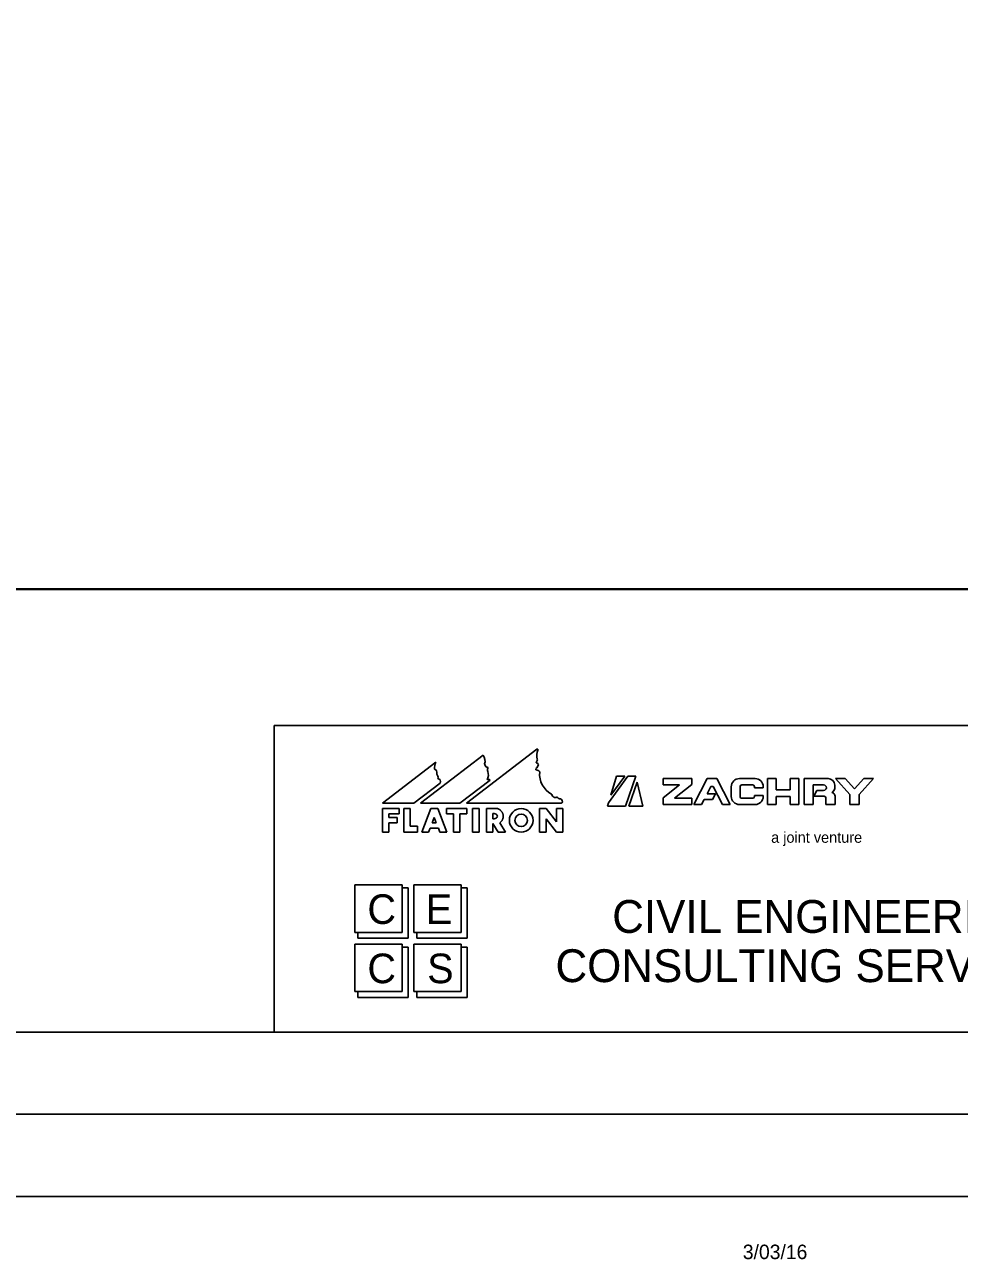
# Model space of a CAD drawing. Extents: x -2251 to 10196, y -13470 to 1199.
# Drawn here: x 6237.7 to 6522.4, y -13469.8 to -13093.7 of the extents above; entities that cross this region are included whole.
import ezdxf

# ---------------------------------------------------------------- set-up
doc = ezdxf.new("R2010")
doc.units = 0
for name, color, linetype in [('Level 3', 7, 'Continuous'), ('RD_SHT_Bndy', 7, 'Continuous'), ('RD_SHT_Iplotshp', 7, 'Continuous'), ('RD_SHT_Logo', 7, 'Continuous'), ('RD_SHT_Misc1', 7, 'Continuous'), ('RD_SHT_Snap', 7, 'Continuous'), ('RD_SHT_TX', 7, 'Continuous'), ('RD_TX_RoadID', 7, 'Continuous')]:
    doc.layers.add(name, color=color, linetype=linetype)

msp = doc.modelspace()

# ---------------------------------------------------------------- linework, layer by layer
at = {"layer": 'Level 3'}
msp.add_line((6465.07, -13363.99), (6465.07, -13363.99), dxfattribs=at)
msp.add_line((6465.07, -13363.99), (6465.07, -13363.99), dxfattribs=at)
msp.add_line((6465.07, -13363.99), (6465.07, -13363.99), dxfattribs=at)
msp.add_line((6465.07, -13363.99), (6465.07, -13363.99), dxfattribs=at)
at = {"layer": 'RD_SHT_Bndy'}
for p, q in [((5103.1, -13400.65), (6778.1, -13400.65)), ((6791.65, -13425.65), (5031.65, -13425.65)), ((6791.6, -13450.7), (5031.6, -13450.65))]:
    msp.add_line(p, q, dxfattribs=at)
msp.add_lwpolyline([(5153.4, -12401.26), (6731.08, -12401.26), (6731.08, -13265.57), (5153.4, -13265.57)], close=True, dxfattribs=at)
at = {"layer": 'RD_SHT_Iplotshp'}
msp.add_lwpolyline([(4996.65, -12325.65), (6796.65, -12325.65), (6796.65, -13425.65), (4996.65, -13425.65)], close=True, dxfattribs=at)
at = {"layer": 'RD_SHT_Logo'}
for p, q in [((6377.35, -13316.27), (6358.31, -13330.86)), ((6372.32, -13330.86), (6393.74, -13314.44)), ((6346.7, -13330.86), (6362.98, -13318.38)), ((6370.3, -13330.86), (6379.48, -13323.82)), ((6415.56, -13330.77), (6421.47, -13322.59)), ((6420.48, -13322.59), (6416.24, -13328.47)), ((6416.24, -13328.47), (6417.96, -13322.59)), ((6417.96, -13322.59), (6420.48, -13322.59)), ((6423.82, -13322.59), (6420.68, -13331.76)), ((6421.47, -13322.59), (6423.82, -13322.59)), ((6440.93, -13323.35), (6432.22, -13323.35)), ((6432.22, -13323.35), (6432.22, -13325.3)), ((6440.93, -13325.16), (6440.93, -13323.35)), ((6445.58, -13323.35), (6441.53, -13331.3)), ((6448.58, -13323.35), (6445.58, -13323.35)), ((6452.63, -13331.3), (6448.58, -13323.35)), ((6455.44, -13323.35), (6460.18, -13323.35)), ((6466.62, -13323.35), (6464.02, -13323.35)), ((6464.02, -13323.35), (6464.02, -13331.3)), ((6466.62, -13326.8), (6466.62, -13323.35)), ((6470.9, -13323.35), (6470.9, -13326.8)), ((6473.51, -13323.35), (6470.9, -13323.35)), ((6473.5, -13331.3), (6473.51, -13323.35)), ((6482.43, -13323.35), (6475.13, -13323.35)), ((6475.13, -13323.35), (6475.13, -13331.3)), ((6484.68, -13323.35), (6487.64, -13323.35)), ((6489.08, -13328.24), (6484.68, -13323.35)), ((6487.64, -13323.35), (6490.48, -13326.51)), ((6490.48, -13326.51), (6493.32, -13323.35)), ((6496.28, -13323.35), (6491.88, -13328.24)), ((6493.32, -13323.35), (6496.28, -13323.35)), ((6364.27, -13324.74), (6356.29, -13330.86)), ((6424.24, -13324.44), (6421.74, -13331.76)), ((6425.99, -13331.76), (6424.24, -13324.44)), ((6437.2, -13325.3), (6432.22, -13329.24)), ((6432.22, -13325.3), (6437.2, -13325.3)), ((6435.63, -13329.35), (6440.93, -13325.16)), ((6445.57, -13327.99), (6446.71, -13325.75)), ((6446.71, -13325.75), (6447.44, -13325.75)), ((6447.44, -13325.75), (6450.27, -13331.3)), ((6452.94, -13328.8), (6452.94, -13325.85)), ((6455.64, -13325.8), (6455.64, -13328.85)), ((6459.48, -13325.3), (6456.14, -13325.3)), ((6459.98, -13326.15), (6459.98, -13325.8)), ((6462.68, -13326.15), (6459.98, -13326.15)), ((6462.68, -13325.85), (6462.68, -13326.15)), ((6470.9, -13326.8), (6466.62, -13326.8)), ((6477.83, -13331.3), (6477.83, -13325.31)), ((6477.83, -13325.31), (6481.07, -13325.31)), ((6479.03, -13326.97), (6478.11, -13328.77)), ((6481.07, -13326.97), (6479.03, -13326.97)), ((6483.68, -13327.6), (6483.68, -13327.47)), ((6484.43, -13326.36), (6484.43, -13325.35)), ((6356.29, -13330.86), (6346.7, -13330.86)), ((6358.31, -13330.86), (6370.3, -13330.86)), ((6401.19, -13330.86), (6372.32, -13330.86)), ((6415.27, -13331.76), (6415.56, -13330.77)), ((6432.22, -13329.24), (6432.22, -13331.3)), ((6432.22, -13331.3), (6440.93, -13331.3)), ((6440.93, -13329.35), (6435.63, -13329.35)), ((6440.93, -13331.3), (6440.93, -13329.35)), ((6441.53, -13331.3), (6443.88, -13331.3)), ((6443.88, -13331.3), (6444.65, -13329.79)), ((6444.65, -13329.79), (6447.23, -13329.79)), ((6448.15, -13327.99), (6445.57, -13327.99)), ((6447.23, -13329.79), (6448.15, -13327.99)), ((6450.27, -13331.3), (6452.63, -13331.3)), ((6460.18, -13331.3), (6455.44, -13331.3)), ((6456.14, -13329.35), (6459.48, -13329.35)), ((6459.98, -13328.5), (6462.68, -13328.5)), ((6459.98, -13328.85), (6459.98, -13328.5)), ((6462.68, -13328.5), (6462.68, -13328.8)), ((6464.02, -13331.3), (6466.62, -13331.3)), ((6466.62, -13331.3), (6466.62, -13328.8)), ((6466.62, -13328.8), (6470.9, -13328.8)), ((6470.9, -13328.8), (6470.9, -13331.3)), ((6470.9, -13331.3), (6473.5, -13331.3)), ((6475.13, -13331.3), (6477.83, -13331.3)), ((6478.11, -13328.77), (6481.24, -13328.77)), ((6481.74, -13329.27), (6481.74, -13331.3)), ((6481.74, -13331.3), (6484.54, -13331.3)), ((6484.54, -13331.3), (6484.54, -13328.76)), ((6489.08, -13331.3), (6489.08, -13328.24)), ((6491.88, -13331.3), (6489.08, -13331.3)), ((6491.88, -13328.24), (6491.88, -13331.3)), ((6346.72, -13339.7), (6346.72, -13332.5)), ((6346.72, -13332.5), (6351.82, -13332.5)), ((6351.82, -13334.15), (6348.67, -13334.15)), ((6348.67, -13334.15), (6348.67, -13335.21)), ((6348.67, -13335.21), (6351.22, -13335.21)), ((6351.22, -13335.21), (6351.22, -13336.86)), ((6351.82, -13332.5), (6351.82, -13334.15)), ((6355.12, -13332.5), (6353.17, -13332.5)), ((6353.17, -13332.5), (6353.17, -13339.7)), ((6355.12, -13337.9), (6355.12, -13332.5)), ((6361.42, -13332.5), (6358.65, -13339.71)), ((6363.52, -13332.5), (6361.42, -13332.5)), ((6361.83, -13336.86), (6362.47, -13335.2)), ((6362.47, -13335.2), (6363.1, -13336.86)), ((6366.28, -13339.71), (6363.52, -13332.5)), ((6366.22, -13334.15), (6366.22, -13332.5)), ((6366.22, -13332.5), (6372.37, -13332.5)), ((6368.32, -13334.15), (6366.22, -13334.15)), ((6368.32, -13339.71), (6368.32, -13334.15)), ((6372.37, -13334.15), (6370.27, -13334.15)), ((6370.27, -13334.15), (6370.27, -13339.71)), ((6372.37, -13332.5), (6372.37, -13334.15)), ((6374.17, -13339.71), (6374.17, -13332.5)), ((6374.17, -13332.5), (6376.12, -13332.5)), ((6376.12, -13332.5), (6376.12, -13339.71)), ((6381.8, -13332.5), (6378.38, -13332.5)), ((6378.38, -13332.5), (6378.38, -13339.71)), ((6380.33, -13335.66), (6380.33, -13334.01)), ((6396.52, -13332.5), (6394.57, -13332.5)), ((6394.57, -13332.5), (6394.57, -13339.71)), ((6399.67, -13336.53), (6396.52, -13332.5)), ((6401.62, -13332.5), (6399.67, -13332.5)), ((6399.67, -13332.5), (6399.67, -13336.53)), ((6401.62, -13339.71), (6401.62, -13332.5)), ((6420.68, -13331.76), (6415.27, -13331.76)), ((6421.74, -13331.76), (6425.99, -13331.76)), ((6351.22, -13336.86), (6348.67, -13336.86)), ((6348.67, -13336.86), (6348.67, -13339.7)), ((6357.37, -13337.9), (6355.12, -13337.9)), ((6357.37, -13339.71), (6357.37, -13337.9)), ((6360.74, -13339.71), (6361.2, -13338.51)), ((6361.2, -13338.51), (6363.74, -13338.51)), ((6363.1, -13336.86), (6361.83, -13336.86)), ((6363.74, -13338.51), (6364.2, -13339.71)), ((6380.33, -13339.71), (6380.33, -13337.02)), ((6380.33, -13337.02), (6381.94, -13339.71)), ((6384.16, -13339.71), (6382.43, -13336.82)), ((6396.52, -13339.71), (6396.52, -13335.67)), ((6396.52, -13335.67), (6399.67, -13339.71)), ((6348.67, -13339.7), (6346.72, -13339.7)), ((6353.17, -13339.7), (6357.37, -13339.71)), ((6358.65, -13339.71), (6360.74, -13339.71)), ((6364.2, -13339.71), (6366.28, -13339.71)), ((6370.27, -13339.71), (6368.32, -13339.71)), ((6376.12, -13339.71), (6374.17, -13339.71)), ((6378.38, -13339.71), (6380.33, -13339.71)), ((6381.94, -13339.71), (6384.16, -13339.71)), ((6394.57, -13339.71), (6396.52, -13339.71)), ((6399.67, -13339.71), (6401.62, -13339.71)), ((6352.67, -13355.79), (6338.28, -13355.79)), ((6338.28, -13355.79), (6338.28, -13370.23)), ((6352.67, -13370.23), (6352.67, -13355.79)), ((6352.67, -13355.79), (6352.67, -13370.23)), ((6354.48, -13356.7), (6352.67, -13356.7)), ((6354.48, -13372.03), (6354.48, -13356.7)), ((6370.67, -13355.79), (6356.27, -13355.79)), ((6356.27, -13355.79), (6356.27, -13370.23)), ((6370.67, -13370.23), (6370.67, -13355.79)), ((6370.67, -13355.79), (6370.67, -13370.23)), ((6372.48, -13356.7), (6370.67, -13356.7)), ((6372.48, -13372.03), (6372.48, -13356.7)), ((6338.28, -13370.23), (6352.67, -13370.23)), ((6352.67, -13370.23), (6339.17, -13370.23)), ((6339.17, -13370.23), (6339.17, -13372.03)), ((6339.17, -13372.03), (6354.48, -13372.03)), ((6356.27, -13370.23), (6370.67, -13370.23)), ((6370.67, -13370.23), (6357.18, -13370.23)), ((6357.18, -13370.23), (6357.18, -13372.03)), ((6357.18, -13372.03), (6372.48, -13372.03)), ((6352.67, -13373.84), (6338.28, -13373.84)), ((6338.28, -13373.84), (6338.28, -13388.27)), ((6352.67, -13388.27), (6352.67, -13373.84)), ((6352.67, -13373.84), (6352.67, -13388.27)), ((6354.48, -13374.74), (6352.67, -13374.74)), ((6354.48, -13390.07), (6354.48, -13374.74)), ((6370.67, -13373.84), (6356.27, -13373.84)), ((6356.27, -13373.84), (6356.27, -13388.27)), ((6370.67, -13388.27), (6370.67, -13373.84)), ((6370.67, -13373.84), (6370.67, -13388.27)), ((6372.48, -13374.74), (6370.67, -13374.74)), ((6372.48, -13390.07), (6372.48, -13374.74)), ((6338.28, -13388.27), (6352.67, -13388.27)), ((6352.67, -13388.27), (6339.17, -13388.27)), ((6339.17, -13388.27), (6339.17, -13390.07)), ((6339.17, -13390.07), (6354.48, -13390.07)), ((6356.27, -13388.27), (6370.67, -13388.27)), ((6370.67, -13388.27), (6357.18, -13388.27)), ((6357.18, -13388.27), (6357.18, -13390.07)), ((6357.18, -13390.07), (6372.48, -13390.07))]:
    msp.add_line(p, q, dxfattribs=at)
for radius in [3.6, 1.9]:
    msp.add_circle((6388.95, -13336.1), radius, dxfattribs=at)
for centre, radius, start, end in [((6375.05, -13318.02), 2.89, 342.0343, 37.2653), ((6397.87, -13316.34), 4.17, 156.4699, 195.3053), ((6393.86, -13314.6), 0.2, 336.4699, 127.4657), ((6366.29, -13320.12), 3.74, 152.2252, 185.8662), ((6377.99, -13318.97), 0.2, 162.0343, 220.8638), ((6376.86, -13319.95), 1.3, 11.8745, 40.8638), ((6378.32, -13319.64), 0.2, 191.8745, 279.8173), ((6378.44, -13320.33), 0.499, 44.4799, 99.8173), ((6379.5, -13320.72), 0.843, 144.641, 212.5499), ((6378.65, -13320.12), 0.2, 324.641, 44.4799), ((6393.57, -13320.5), 0.2, 133.0036, 262.3069), ((6391.59, -13318.37), 2.7, 313.0036, 343.6807), ((6393.73, -13318.39), 0.2, 129.4079, 246.863), ((6393.13, -13317.66), 0.749, 309.4079, 17.0499), ((6393.27, -13319.47), 0.973, 20.4113, 66.863), ((6362.1, -13321.62), 1.21, 351.6466, 67.1294), ((6364.29, -13321.94), 1, 171.6466, 221.9371), ((6363.11, -13323.01), 0.592, 327.6019, 41.9371), ((6363.3, -13324.33), 1.05, 337.4201, 73.1261), ((6375.8, -13322.18), 3.16, 331.2486, 18.4584), ((6378.92, -13324.44), 0.827, 48.0701, 115.7229), ((6393.31, -13322.44), 1.76, 45.283, 82.3069), ((6394.4, -13321.33), 0.2, 353.8329, 45.283), ((6401.36, -13322.08), 6.8, 173.8329, 242.3928), ((6455.44, -13325.85), 2.5, 89.9984, 179.9984), ((6460.18, -13325.85), 2.5, 359.9984, 89.9984), ((6482.43, -13325.35), 2, 359.9984, 89.9984), ((6456.14, -13325.8), 0.5, 89.9984, 179.9984), ((6459.48, -13325.8), 0.5, 359.9984, 89.9984), ((6481.07, -13326.14), 0.831, 269.9984, 89.9984), ((6483.23, -13326.36), 1.2, 291.95, 359.9984), ((6483.34, -13328.76), 1.2, 359.9984, 73.7977), ((6398.12, -13328.28), 0.2, 9.0833, 62.3928), ((6399.35, -13328.09), 1.04, 189.0833, 295.769), ((6399.89, -13329.21), 0.2, 33.7112, 115.769), ((6400.89, -13328.54), 1.01, 213.7112, 268.6299), ((6400.86, -13329.74), 0.2, 78.9712, 88.6299), ((6400.75, -13330.3), 0.767, 320.912, 78.9712), ((6401.19, -13330.66), 0.2, 269.9984, 320.912), ((6455.44, -13328.8), 2.5, 179.9984, 269.9984), ((6456.14, -13328.85), 0.5, 179.9984, 269.9984), ((6459.48, -13328.85), 0.5, 269.9984, 359.9984), ((6460.18, -13328.8), 2.5, 269.9984, 359.9984), ((6481.24, -13329.27), 0.5, 359.9984, 89.9984)]:
    msp.add_arc(centre, radius, start, end, dxfattribs=at)
msp.add_ellipse((6380.33, -13334.83), major_axis=(1.36, 0), ratio=0.609965, start_param=4.712389, end_param=7.853982, dxfattribs=at)
msp.add_open_spline([(6382.43, -13336.82), (6382.51, -13336.76), (6382.59, -13336.7), (6382.81, -13336.49), (6382.95, -13336.34), (6383.13, -13336.07), (6383.19, -13335.97), (6383.29, -13335.77), (6383.34, -13335.66), (6383.41, -13335.44), (6383.44, -13335.32), (6383.47, -13335.08), (6383.48, -13334.96), (6383.48, -13334.71), (6383.47, -13334.59), (6383.44, -13334.35), (6383.41, -13334.23), (6383.34, -13334.01), (6383.29, -13333.9), (6383.19, -13333.7), (6383.13, -13333.6), (6382.95, -13333.33), (6382.81, -13333.18), (6382.52, -13332.91), (6382.37, -13332.8), (6382.08, -13332.63), (6381.94, -13332.56), (6381.8, -13332.5)], degree=3, dxfattribs=at)
at = {"layer": 'RD_SHT_Misc1'}
msp.add_lwpolyline([(6796.65, -13425.65), (6796.68, -12325.65), (5096.68, -12325.6), (5096.65, -13425.6)], close=True, dxfattribs=at)
at = {"layer": 'RD_SHT_Snap'}
msp.add_lwpolyline([(5008.15, -12325.65), (6808.15, -12325.65), (6808.15, -13425.65), (5008.15, -13425.65)], close=True, dxfattribs=at)
at = {"layer": 'RD_SHT_TX'}
for p, q in [((6313.76, -13400.65), (6313.76, -13307.15)), ((6313.76, -13400.65), (6313.76, -13307.15)), ((6313.76, -13307.15), (6778.1, -13307.15))]:
    msp.add_line(p, q, dxfattribs=at)
at = {"layer": 'RD_TX_RoadID'}
msp.add_lwpolyline([(5150.54, -13265.73), (6733.93, -13265.73), (6733.93, -12462.61), (5150.54, -12462.61)], close=True, dxfattribs=at)

# ---------------------------------------------------------------- texts
at = {"layer": 'RD_SHT_Logo'}
msp.add_text('a joint venture', height=3.3, rotation=359.9984, dxfattribs=at).set_placement((6465.08, -13342.93))
for s, height, p in [('C', 9.02, (6342.11, -13367.66)), ('E', 9.02, (6359.9, -13367.66)), ('CIVIL ENGINEERING', 10, (6416.67, -13370.38)), ('C', 9.02, (6342.11, -13385.71)), ('S', 9.02, (6360.32, -13385.71)), ('CONSULTING SERVICES, INC.', 10, (6399.39, -13385.38))]:
    msp.add_text(s, height=height, dxfattribs=at).set_placement(p)
at = {"layer": 'RD_SHT_TX'}
msp.add_text('3/03/16', height=4.408, dxfattribs=at).set_placement((6456.45, -13469.78))

doc.saveas('drawing.dxf')
